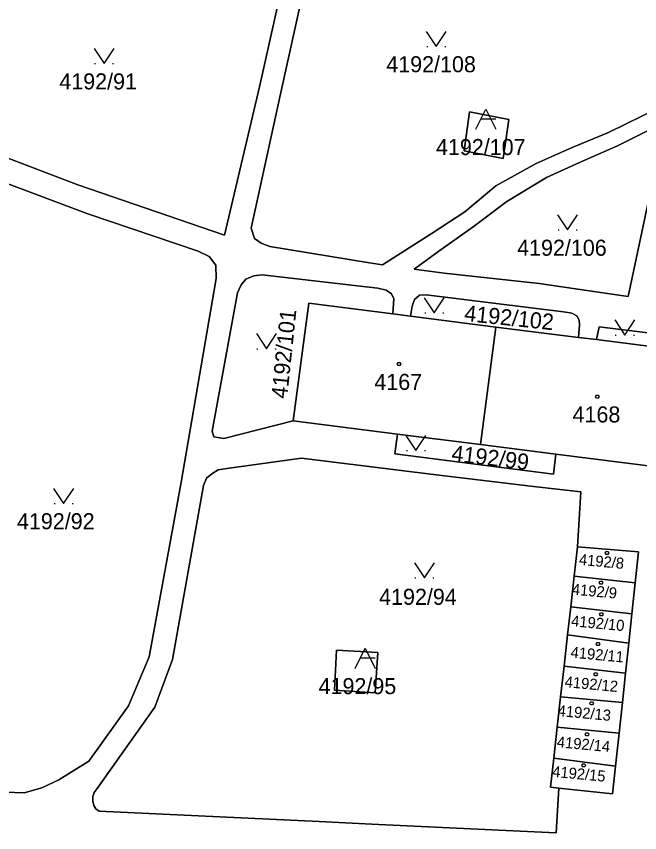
# Model space of a CAD drawing. Extents: x -263587 to -261993, y -1238795 to -1236748.
# Drawn here: x -262969.2 to -262907.1, y -1237790.6 to -1237709.3 of the extents above; entities that cross this region are included whole.
import ezdxf

# ---------------------------------------------------------------- set-up
doc = ezdxf.new("R2010")
doc.units = 0
doc.layers.add('Vrstva 1', color=7, linetype='Continuous')

msp = doc.modelspace()

# ---------------------------------------------------------------- linework, layer by layer
at = {"layer": 'Vrstva 1'}
for p, q in [((-262944.95, -1237716.28), (-262941.7, -1237701.72)), ((-262941.7, -1237701.72), (-262944.95, -1237716.28)), ((-262939.59, -1237702.2), (-262942.91, -1237717.15)), ((-262942.91, -1237717.15), (-262939.59, -1237702.2)), ((-262928.3, -1237712.27), (-262928.2, -1237712.27)), ((-262926.5, -1237712.27), (-262926.4, -1237712.27)), ((-262961.39, -1237713.98), (-262961.29, -1237713.98)), ((-262959.59, -1237713.98), (-262959.49, -1237713.98)), ((-262948.45, -1237731.06), (-262944.95, -1237716.28)), ((-262944.95, -1237716.28), (-262948.45, -1237731.06)), ((-262942.91, -1237717.15), (-262945.78, -1237730.37)), ((-262945.78, -1237730.37), (-262942.91, -1237717.15)), ((-262910.18, -1237720.85), (-262904.17, -1237717.88)), ((-262904.17, -1237717.88), (-262910.18, -1237720.85)), ((-262924.04, -1237718.78), (-262924.56, -1237722.67)), ((-262924.56, -1237722.67), (-262924.04, -1237718.78)), ((-262920.11, -1237719.53), (-262924.04, -1237718.78)), ((-262924.04, -1237718.78), (-262920.11, -1237719.53)), ((-262921.4, -1237719.52), (-262922.9, -1237719.52)), ((-262920.67, -1237723.43), (-262920.11, -1237719.53)), ((-262920.11, -1237719.53), (-262920.67, -1237723.43)), ((-262904.56, -1237719.8), (-262909.29, -1237722.18)), ((-262909.29, -1237722.18), (-262904.56, -1237719.8)), ((-262908.22, -1237737.19), (-262904.56, -1237719.8)), ((-262904.56, -1237719.8), (-262908.22, -1237737.19)), ((-262913.81, -1237722.34), (-262910.18, -1237720.85)), ((-262910.18, -1237720.85), (-262913.81, -1237722.34)), ((-262975.19, -1237721.42), (-262963.05, -1237726.05)), ((-262963.05, -1237726.05), (-262975.19, -1237721.42)), ((-262924.56, -1237722.67), (-262920.67, -1237723.43)), ((-262920.67, -1237723.43), (-262924.56, -1237722.67)), ((-262917.38, -1237723.94), (-262913.81, -1237722.34)), ((-262913.81, -1237722.34), (-262917.38, -1237723.94)), ((-262909.29, -1237722.18), (-262913.07, -1237723.82)), ((-262913.07, -1237723.82), (-262909.29, -1237722.18)), ((-262921.43, -1237726.14), (-262917.38, -1237723.94)), ((-262917.38, -1237723.94), (-262921.43, -1237726.14)), ((-262913.07, -1237723.82), (-262916.38, -1237725.32)), ((-262916.38, -1237725.32), (-262913.07, -1237723.82)), ((-262962.05, -1237728.94), (-262970.2, -1237725.9)), ((-262970.2, -1237725.9), (-262962.05, -1237728.94)), ((-262916.38, -1237725.32), (-262920.32, -1237727.73)), ((-262920.32, -1237727.73), (-262916.38, -1237725.32)), ((-262963.05, -1237726.05), (-262948.45, -1237731.06)), ((-262948.45, -1237731.06), (-262963.05, -1237726.05)), ((-262924.49, -1237728.73), (-262921.43, -1237726.14)), ((-262921.43, -1237726.14), (-262924.49, -1237728.73)), ((-262920.32, -1237727.73), (-262923.67, -1237730.24)), ((-262923.67, -1237730.24), (-262920.32, -1237727.73)), ((-262951.07, -1237732.65), (-262962.05, -1237728.94)), ((-262962.05, -1237728.94), (-262951.07, -1237732.65)), ((-262927.85, -1237730.95), (-262924.49, -1237728.73)), ((-262924.49, -1237728.73), (-262927.85, -1237730.95)), ((-262945.78, -1237730.37), (-262945.47, -1237731.41)), ((-262945.47, -1237731.41), (-262945.78, -1237730.37)), ((-262923.67, -1237730.24), (-262927.1, -1237732.67)), ((-262927.1, -1237732.67), (-262923.67, -1237730.24)), ((-262915.22, -1237730.55), (-262915.12, -1237730.55)), ((-262913.42, -1237730.55), (-262913.32, -1237730.55)), ((-262945.47, -1237731.41), (-262944.8, -1237731.87)), ((-262944.8, -1237731.87), (-262945.47, -1237731.41)), ((-262932.72, -1237734.02), (-262927.85, -1237730.95)), ((-262927.85, -1237730.95), (-262932.72, -1237734.02)), ((-262944.8, -1237731.87), (-262943.94, -1237732.2)), ((-262943.94, -1237732.2), (-262944.8, -1237731.87)), ((-262943.94, -1237732.2), (-262934, -1237733.81)), ((-262934, -1237733.81), (-262943.94, -1237732.2)), ((-262949.96, -1237733.18), (-262951.07, -1237732.65)), ((-262951.07, -1237732.65), (-262949.96, -1237733.18)), ((-262949.32, -1237734.05), (-262949.96, -1237733.18)), ((-262949.96, -1237733.18), (-262949.32, -1237734.05)), ((-262927.1, -1237732.67), (-262929.54, -1237734.46)), ((-262929.54, -1237734.46), (-262927.1, -1237732.67)), ((-262949.29, -1237735.39), (-262949.32, -1237734.05)), ((-262949.32, -1237734.05), (-262949.29, -1237735.39)), ((-262934, -1237733.81), (-262932.72, -1237734.02)), ((-262932.72, -1237734.02), (-262934, -1237733.81)), ((-262929.54, -1237734.46), (-262926.55, -1237734.85)), ((-262926.55, -1237734.85), (-262929.54, -1237734.46)), ((-262926.55, -1237734.85), (-262917.09, -1237735.88)), ((-262917.09, -1237735.88), (-262926.55, -1237734.85)), ((-262952.81, -1237755.89), (-262949.29, -1237735.39)), ((-262949.29, -1237735.39), (-262952.81, -1237755.89)), ((-262946.33, -1237735.45), (-262946.79, -1237736.02)), ((-262946.79, -1237736.02), (-262946.33, -1237735.45)), ((-262945.54, -1237735.12), (-262946.33, -1237735.45)), ((-262946.33, -1237735.45), (-262945.54, -1237735.12)), ((-262944.69, -1237735.03), (-262945.54, -1237735.12)), ((-262945.54, -1237735.12), (-262944.69, -1237735.03)), ((-262936.35, -1237735.99), (-262944.69, -1237735.03)), ((-262944.69, -1237735.03), (-262936.35, -1237735.99)), ((-262946.79, -1237736.02), (-262947.16, -1237736.81)), ((-262947.16, -1237736.81), (-262946.79, -1237736.02)), ((-262933.18, -1237736.34), (-262936.35, -1237735.99)), ((-262936.35, -1237735.99), (-262933.18, -1237736.34)), ((-262932.35, -1237736.55), (-262933.18, -1237736.34)), ((-262933.18, -1237736.34), (-262932.35, -1237736.55)), ((-262931.8, -1237736.91), (-262932.35, -1237736.55)), ((-262932.35, -1237736.55), (-262931.8, -1237736.91)), ((-262917.09, -1237735.88), (-262912.11, -1237736.63)), ((-262912.11, -1237736.63), (-262917.09, -1237735.88)), ((-262947.16, -1237736.81), (-262949.69, -1237750.6)), ((-262949.69, -1237750.6), (-262947.16, -1237736.81)), ((-262931.58, -1237737.42), (-262931.8, -1237736.91)), ((-262931.8, -1237736.91), (-262931.58, -1237737.42)), ((-262929.01, -1237737.06), (-262929.52, -1237737.49)), ((-262929.52, -1237737.49), (-262929.01, -1237737.06)), ((-262928.37, -1237737.03), (-262929.01, -1237737.06)), ((-262929.01, -1237737.06), (-262928.37, -1237737.03)), ((-262914.67, -1237738.7), (-262928.37, -1237737.03)), ((-262928.37, -1237737.03), (-262914.67, -1237738.7)), ((-262912.11, -1237736.63), (-262908.22, -1237737.19)), ((-262908.22, -1237737.19), (-262912.11, -1237736.63)), ((-262940.04, -1237737.86), (-262940.17, -1237738.84)), ((-262940.17, -1237738.84), (-262940.04, -1237737.86)), ((-262931.67, -1237738.92), (-262940.04, -1237737.86)), ((-262940.04, -1237737.86), (-262931.67, -1237738.92)), ((-262931.67, -1237738.92), (-262931.58, -1237737.42)), ((-262931.58, -1237737.42), (-262931.67, -1237738.92)), ((-262929.76, -1237738.15), (-262929.93, -1237739.14)), ((-262929.93, -1237739.14), (-262929.76, -1237738.15)), ((-262929.52, -1237737.49), (-262929.76, -1237738.15)), ((-262929.76, -1237738.15), (-262929.52, -1237737.49)), ((-262940.17, -1237738.84), (-262941.62, -1237749.56)), ((-262941.62, -1237749.56), (-262940.17, -1237738.84)), ((-262929.93, -1237739.14), (-262931.67, -1237738.92)), ((-262931.67, -1237738.92), (-262929.93, -1237739.14)), ((-262928.5, -1237738.8), (-262928.4, -1237738.8)), ((-262926.7, -1237738.8), (-262926.6, -1237738.8)), ((-262913.85, -1237738.85), (-262914.67, -1237738.7)), ((-262914.67, -1237738.7), (-262913.85, -1237738.85)), ((-262913.35, -1237739.11), (-262913.85, -1237738.85)), ((-262913.85, -1237738.85), (-262913.35, -1237739.11)), ((-262929.93, -1237739.14), (-262921.4, -1237740.22)), ((-262921.4, -1237740.22), (-262929.93, -1237739.14)), ((-262913.12, -1237739.53), (-262913.35, -1237739.11)), ((-262913.35, -1237739.11), (-262913.12, -1237739.53)), ((-262913.09, -1237740.03), (-262913.12, -1237739.53)), ((-262913.12, -1237739.53), (-262913.09, -1237740.03)), ((-262921.4, -1237740.22), (-262922.95, -1237751.93)), ((-262922.95, -1237751.93), (-262921.4, -1237740.22)), ((-262913.17, -1237741.25), (-262921.4, -1237740.22)), ((-262921.4, -1237740.22), (-262913.17, -1237741.25)), ((-262913.17, -1237741.25), (-262913.09, -1237740.03)), ((-262913.09, -1237740.03), (-262913.17, -1237741.25)), ((-262911.13, -1237740.2), (-262911.37, -1237741.48)), ((-262911.37, -1237741.48), (-262911.13, -1237740.2)), ((-262894.88, -1237742.23), (-262911.13, -1237740.2)), ((-262911.13, -1237740.2), (-262894.88, -1237742.23)), ((-262911.37, -1237741.48), (-262913.17, -1237741.25)), ((-262913.17, -1237741.25), (-262911.37, -1237741.48)), ((-262909.51, -1237741.02), (-262909.41, -1237741.02)), ((-262907.71, -1237741.02), (-262907.61, -1237741.02)), ((-262899.48, -1237742.98), (-262911.37, -1237741.48)), ((-262911.37, -1237741.48), (-262899.48, -1237742.98)), ((-262945.21, -1237742.38), (-262945.11, -1237742.38)), ((-262943.41, -1237742.38), (-262943.31, -1237742.38)), ((-262948.52, -1237751.34), (-262941.62, -1237749.56)), ((-262941.62, -1237749.56), (-262948.52, -1237751.34)), ((-262941.62, -1237749.56), (-262931.2, -1237750.88)), ((-262931.2, -1237750.88), (-262941.62, -1237749.56)), ((-262949.69, -1237750.6), (-262949.5, -1237751.17)), ((-262949.5, -1237751.17), (-262949.69, -1237750.6)), ((-262949.5, -1237751.17), (-262948.52, -1237751.34)), ((-262948.52, -1237751.34), (-262949.5, -1237751.17)), ((-262931.2, -1237750.88), (-262931.46, -1237752.87)), ((-262931.46, -1237752.87), (-262931.2, -1237750.88)), ((-262931.2, -1237750.88), (-262922.95, -1237751.93)), ((-262922.95, -1237751.93), (-262931.2, -1237750.88)), ((-262922.95, -1237751.93), (-262915.43, -1237752.89)), ((-262915.43, -1237752.89), (-262922.95, -1237751.93)), ((-262930.33, -1237752.52), (-262930.23, -1237752.52)), ((-262928.53, -1237752.52), (-262928.43, -1237752.52)), ((-262948.21, -1237754.33), (-262940.77, -1237753.28)), ((-262940.77, -1237753.28), (-262948.21, -1237754.33)), ((-262940.77, -1237753.28), (-262927.61, -1237754.92)), ((-262927.61, -1237754.92), (-262940.77, -1237753.28)), ((-262931.46, -1237752.87), (-262915.68, -1237754.87)), ((-262915.68, -1237754.87), (-262931.46, -1237752.87)), ((-262915.68, -1237754.87), (-262915.43, -1237752.89)), ((-262915.43, -1237752.89), (-262915.68, -1237754.87)), ((-262915.43, -1237752.89), (-262901.08, -1237754.72)), ((-262901.08, -1237754.72), (-262915.43, -1237752.89)), ((-262949.07, -1237754.45), (-262948.21, -1237754.33)), ((-262948.21, -1237754.33), (-262949.07, -1237754.45)), ((-262950.24, -1237755.29), (-262949.7, -1237754.84)), ((-262949.7, -1237754.84), (-262950.24, -1237755.29)), ((-262949.7, -1237754.84), (-262949.07, -1237754.45)), ((-262949.07, -1237754.45), (-262949.7, -1237754.84)), ((-262927.61, -1237754.92), (-262917.65, -1237756.1)), ((-262917.65, -1237756.1), (-262927.61, -1237754.92)), ((-262955.96, -1237773.08), (-262952.81, -1237755.89)), ((-262952.81, -1237755.89), (-262955.96, -1237773.08)), ((-262953.63, -1237773.34), (-262950.55, -1237756)), ((-262950.55, -1237756), (-262953.63, -1237773.34)), ((-262950.55, -1237756), (-262950.24, -1237755.29)), ((-262950.24, -1237755.29), (-262950.55, -1237756)), ((-262917.65, -1237756.1), (-262912.95, -1237756.63)), ((-262912.95, -1237756.63), (-262917.65, -1237756.1)), ((-262912.95, -1237756.63), (-262913.28, -1237762.13)), ((-262913.28, -1237762.13), (-262912.95, -1237756.63)), ((-262965.42, -1237757.8), (-262965.32, -1237757.8)), ((-262963.62, -1237757.8), (-262963.52, -1237757.8)), ((-262913.61, -1237765.05), (-262913.28, -1237762.13)), ((-262913.28, -1237762.13), (-262913.61, -1237765.05)), ((-262913.28, -1237762.13), (-262907.19, -1237762.61)), ((-262907.19, -1237762.61), (-262913.28, -1237762.13)), ((-262907.19, -1237762.61), (-262907.52, -1237765.72)), ((-262907.52, -1237765.72), (-262907.19, -1237762.61)), ((-262929.48, -1237765.22), (-262929.38, -1237765.22)), ((-262927.68, -1237765.22), (-262927.58, -1237765.22)), ((-262913.95, -1237768.09), (-262913.61, -1237765.05)), ((-262913.61, -1237765.05), (-262913.95, -1237768.09)), ((-262913.61, -1237765.05), (-262907.52, -1237765.72)), ((-262907.52, -1237765.72), (-262913.61, -1237765.05)), ((-262907.52, -1237765.72), (-262907.86, -1237768.8)), ((-262907.86, -1237768.8), (-262907.52, -1237765.72)), ((-262914.26, -1237770.9), (-262913.95, -1237768.09)), ((-262913.95, -1237768.09), (-262914.26, -1237770.9)), ((-262913.95, -1237768.09), (-262907.86, -1237768.8)), ((-262907.86, -1237768.8), (-262913.95, -1237768.09)), ((-262907.86, -1237768.8), (-262908.17, -1237771.72)), ((-262908.17, -1237771.72), (-262907.86, -1237768.8)), ((-262914.61, -1237774), (-262914.26, -1237770.9)), ((-262914.26, -1237770.9), (-262914.61, -1237774)), ((-262914.26, -1237770.9), (-262908.17, -1237771.72)), ((-262908.17, -1237771.72), (-262914.26, -1237770.9)), ((-262908.17, -1237771.72), (-262908.49, -1237774.71)), ((-262908.49, -1237774.71), (-262908.17, -1237771.72)), ((-262958, -1237777.95), (-262955.96, -1237773.08)), ((-262955.96, -1237773.08), (-262958, -1237777.95)), ((-262937.28, -1237772.41), (-262937.5, -1237776.39)), ((-262937.5, -1237776.39), (-262937.28, -1237772.41)), ((-262933.17, -1237772.64), (-262937.28, -1237772.41)), ((-262937.28, -1237772.41), (-262933.17, -1237772.64)), ((-262933.45, -1237776.67), (-262933.17, -1237772.64)), ((-262933.17, -1237772.64), (-262933.45, -1237776.67)), ((-262955.38, -1237778.08), (-262953.63, -1237773.34)), ((-262953.63, -1237773.34), (-262955.38, -1237778.08)), ((-262933.42, -1237773.23), (-262934.92, -1237773.23)), ((-262914.96, -1237777.06), (-262914.61, -1237774)), ((-262914.61, -1237774), (-262914.96, -1237777.06)), ((-262914.61, -1237774), (-262908.49, -1237774.71)), ((-262908.49, -1237774.71), (-262914.61, -1237774)), ((-262908.49, -1237774.71), (-262908.81, -1237777.63)), ((-262908.81, -1237777.63), (-262908.49, -1237774.71)), ((-262937.5, -1237776.39), (-262933.45, -1237776.67)), ((-262933.45, -1237776.67), (-262937.5, -1237776.39)), ((-262915.3, -1237780.08), (-262914.96, -1237777.06)), ((-262914.96, -1237777.06), (-262915.3, -1237780.08)), ((-262914.96, -1237777.06), (-262908.81, -1237777.63)), ((-262908.81, -1237777.63), (-262914.96, -1237777.06)), ((-262961.97, -1237783.49), (-262958, -1237777.95)), ((-262958, -1237777.95), (-262961.97, -1237783.49)), ((-262908.81, -1237777.63), (-262909.14, -1237780.7)), ((-262909.14, -1237780.7), (-262908.81, -1237777.63)), ((-262961.12, -1237786.19), (-262955.38, -1237778.08)), ((-262955.38, -1237778.08), (-262961.12, -1237786.19)), ((-262915.65, -1237783.18), (-262915.3, -1237780.08)), ((-262915.3, -1237780.08), (-262915.65, -1237783.18)), ((-262909.14, -1237780.7), (-262915.3, -1237780.08)), ((-262915.3, -1237780.08), (-262909.14, -1237780.7)), ((-262909.14, -1237780.7), (-262909.5, -1237783.99)), ((-262909.5, -1237783.99), (-262909.14, -1237780.7)), ((-262964.96, -1237785.34), (-262961.97, -1237783.49)), ((-262961.97, -1237783.49), (-262964.96, -1237785.34)), ((-262915.97, -1237786.08), (-262915.65, -1237783.18)), ((-262915.65, -1237783.18), (-262915.97, -1237786.08)), ((-262909.5, -1237783.99), (-262915.65, -1237783.18)), ((-262915.65, -1237783.18), (-262909.5, -1237783.99)), ((-262909.5, -1237783.99), (-262909.79, -1237786.74)), ((-262909.79, -1237786.74), (-262909.5, -1237783.99)), ((-262966.64, -1237786.13), (-262964.96, -1237785.34)), ((-262964.96, -1237785.34), (-262966.64, -1237786.13)), ((-262968.41, -1237786.64), (-262966.64, -1237786.13)), ((-262966.64, -1237786.13), (-262968.41, -1237786.64)), ((-262915.13, -1237786.17), (-262915.97, -1237786.08)), ((-262915.97, -1237786.08), (-262915.13, -1237786.17)), ((-262970.32, -1237786.58), (-262968.41, -1237786.64)), ((-262968.41, -1237786.64), (-262970.32, -1237786.58)), ((-262961.56, -1237786.98), (-262961.44, -1237786.61)), ((-262961.44, -1237786.61), (-262961.56, -1237786.98)), ((-262961.44, -1237786.61), (-262961.12, -1237786.19)), ((-262961.12, -1237786.19), (-262961.44, -1237786.61)), ((-262915.13, -1237786.17), (-262915.39, -1237790.6)), ((-262915.39, -1237790.6), (-262915.13, -1237786.17)), ((-262909.79, -1237786.74), (-262915.13, -1237786.17)), ((-262915.13, -1237786.17), (-262909.79, -1237786.74)), ((-262961.58, -1237787.47), (-262961.56, -1237786.98)), ((-262961.56, -1237786.98), (-262961.58, -1237787.47)), ((-262961.46, -1237787.88), (-262961.58, -1237787.47)), ((-262961.58, -1237787.47), (-262961.46, -1237787.88)), ((-262961.27, -1237788.23), (-262961.46, -1237787.88)), ((-262961.46, -1237787.88), (-262961.27, -1237788.23)), ((-262960.93, -1237788.47), (-262961.27, -1237788.23)), ((-262961.27, -1237788.23), (-262960.93, -1237788.47)), ((-262939.03, -1237789.5), (-262960.93, -1237788.47)), ((-262960.93, -1237788.47), (-262939.03, -1237789.5)), ((-262933.76, -1237789.75), (-262939.03, -1237789.5)), ((-262939.03, -1237789.5), (-262933.76, -1237789.75)), ((-262918.98, -1237790.45), (-262933.76, -1237789.75)), ((-262933.76, -1237789.75), (-262918.98, -1237790.45)), ((-262915.39, -1237790.6), (-262918.98, -1237790.45)), ((-262918.98, -1237790.45), (-262915.39, -1237790.6))]:
    msp.add_line(p, q, dxfattribs=at)
for points in [[(-262928.35, -1237710.77), (-262927.35, -1237712.27), (-262926.35, -1237710.77)], [(-262961.44, -1237712.48), (-262960.44, -1237713.98), (-262959.44, -1237712.48)], [(-262923.4, -1237720.52), (-262922.4, -1237718.52), (-262921.4, -1237720.52)], [(-262915.27, -1237729.05), (-262914.27, -1237730.55), (-262913.27, -1237729.05)], [(-262928.55, -1237737.3), (-262927.55, -1237738.8), (-262926.55, -1237737.3)], [(-262909.56, -1237739.52), (-262908.56, -1237741.02), (-262907.56, -1237739.52)], [(-262945.26, -1237740.88), (-262944.26, -1237742.38), (-262943.26, -1237740.88)], [(-262930.38, -1237751.02), (-262929.38, -1237752.52), (-262928.38, -1237751.02)], [(-262965.47, -1237756.3), (-262964.47, -1237757.8), (-262963.47, -1237756.3)], [(-262929.53, -1237763.72), (-262928.53, -1237765.22), (-262927.53, -1237763.72)], [(-262935.42, -1237774.23), (-262934.42, -1237772.23), (-262933.42, -1237774.23)]]:
    msp.add_lwpolyline(points, dxfattribs=at)
for points in [[(-262930.97, -1237743.77), (-262930.88, -1237743.92), (-262930.97, -1237744.07), (-262931.15, -1237744.07), (-262931.24, -1237743.92), (-262931.15, -1237743.77)], [(-262911.22, -1237747.01), (-262911.13, -1237747.16), (-262911.22, -1237747.31), (-262911.4, -1237747.31), (-262911.49, -1237747.16), (-262911.4, -1237747.01)], [(-262910.24, -1237762.57), (-262910.15, -1237762.72), (-262910.24, -1237762.87), (-262910.42, -1237762.87), (-262910.51, -1237762.72), (-262910.42, -1237762.57)], [(-262910.84, -1237765.53), (-262910.75, -1237765.68), (-262910.84, -1237765.83), (-262911.02, -1237765.83), (-262911.11, -1237765.68), (-262911.02, -1237765.53)], [(-262910.82, -1237768.69), (-262910.73, -1237768.84), (-262910.82, -1237768.99), (-262911, -1237768.99), (-262911.09, -1237768.84), (-262911, -1237768.69)], [(-262911.14, -1237771.64), (-262911.05, -1237771.79), (-262911.14, -1237771.94), (-262911.32, -1237771.94), (-262911.41, -1237771.79), (-262911.32, -1237771.64)], [(-262911.38, -1237774.67), (-262911.29, -1237774.82), (-262911.38, -1237774.97), (-262911.56, -1237774.97), (-262911.65, -1237774.82), (-262911.56, -1237774.67)], [(-262911.79, -1237777.56), (-262911.7, -1237777.71), (-262911.79, -1237777.86), (-262911.97, -1237777.86), (-262912.06, -1237777.71), (-262911.97, -1237777.56)], [(-262912.23, -1237780.66), (-262912.14, -1237780.81), (-262912.23, -1237780.96), (-262912.41, -1237780.96), (-262912.5, -1237780.81), (-262912.41, -1237780.66)], [(-262912.56, -1237783.75), (-262912.47, -1237783.9), (-262912.56, -1237784.05), (-262912.74, -1237784.05), (-262912.83, -1237783.9), (-262912.74, -1237783.75)]]:
    msp.add_lwpolyline(points, close=True, dxfattribs=at)

# ---------------------------------------------------------------- texts
for s, p in [('4192/108', (-262932.328, -1237714.84)), ('4192/91', (-262964.901, -1237716.55)), ('4192/107', (-262927.378, -1237723.09)), ('4192/106', (-262919.292, -1237733.12)), ('4167', (-262933.518, -1237746.49)), ('4168', (-262913.768, -1237749.73)), ('4192/92', (-262969.12, -1237760.37)), ('4192/94', (-262933.04, -1237767.9)), ('4192/95', (-262939.07, -1237776.8))]:
    msp.add_text(s, height=1.6, dxfattribs=at).set_placement(p)
for s, height, rotation, p in [('4192/102', 1.6, 354.03062, (-262924.608, -1237739.611)), ('4192/101', 1.6, 83.99561, (-262942.213, -1237747.411)), ('4192/99', 1.6, 353.17119, (-262925.896, -1237753.566)), ('4192/8', 1.1, 354.60358, (-262913.173, -1237763.908)), ('4192/9', 1.1, 354.60358, (-262913.877, -1237766.868)), ('4192/10', 1.1, 354.60358, (-262913.951, -1237770.027)), ('4192/11', 1.1, 354.60358, (-262914.004, -1237773.153)), ('4192/12', 1.1, 354.60358, (-262914.594, -1237776.091)), ('4192/13', 1.1, 354.60358, (-262915.294, -1237778.971)), ('4192/14', 1.1, 354.60358, (-262915.374, -1237782.081)), ('4192/15', 1.1, 354.60358, (-262915.834, -1237785.031))]:
    msp.add_text(s, height=height, rotation=rotation, dxfattribs=at).set_placement(p)

doc.saveas('drawing.dxf')
